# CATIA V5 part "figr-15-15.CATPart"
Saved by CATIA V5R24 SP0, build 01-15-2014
Part number: Part1
Bounding box of the stored display mesh (mm): x -75 to 75, y -66.397 to 33.603, z 0 to 1
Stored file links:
  D:\KAVITA\CATIA V5-6R2014 Project_ Kavita\CATIA V5-6R2014_partfiles\Partfiles\c15_catia_v5-6r2014_prt\figr-15-15.CATPart
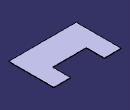
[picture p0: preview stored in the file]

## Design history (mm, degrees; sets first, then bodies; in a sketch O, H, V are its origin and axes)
SheetMetalParameters1: Thickness 1, BendRadius 1, KFactor 0.325257 {= log(min(100,max(20*SheetMetalParameters1.BendRadius,SheetMetalParameters1.Thickness)/SheetMetalParameters1.Thickness))/log(100)/2}, ReliefRadialLength 1, ReliefAxialLength 2, MinimumBendRadius 0
Body1 (main body)
  Sketch1 on xy-plane, origin (0, 0, 0), H (1, 0, 0), V (0, 1, 0)
    line L1 (-37.5, 33.6029) -> (-37.5, -6.3971)
    line L2 (-37.5, -6.3971) -> (37.5, -6.3971)
    line L3 (37.5, -6.3971) -> (37.5, 33.6029)
    line L4 (37.5, 33.6029) -> (75, 33.6029)
    line L5 (75, 33.6029) -> (75, -66.3971)
    line L6 (75, -66.3971) -> (-75, -66.3971)
    line L7 (-75, -66.3971) -> (-75, 33.6029)
    point P8 (-75, 33.6029)
    line L8 (-75, 33.6029) -> (-37.5, 33.6029)
    length L7 = 100
    length L1 = 40
    length L6 = 150
    distance L1 L3 = 75
    vertical: L1 V, L3 V, L5 V, L7 V
    horizontal: L2 H, L4 H, L6 H, L8 H
    coincidence: P8 L4
    symmetry: L7 L5 V, L1 L3 V
  Wall1: Thickness 1, Profile Sketch1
